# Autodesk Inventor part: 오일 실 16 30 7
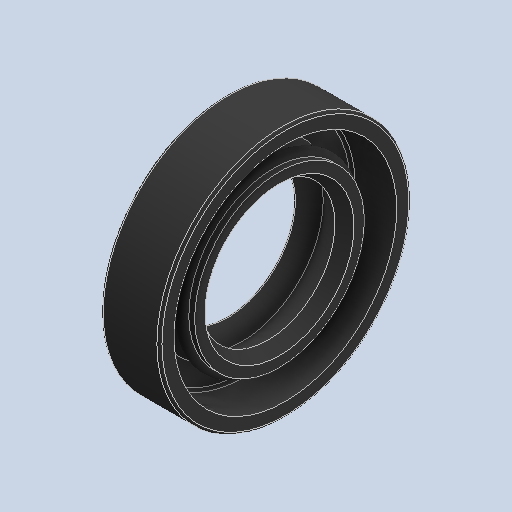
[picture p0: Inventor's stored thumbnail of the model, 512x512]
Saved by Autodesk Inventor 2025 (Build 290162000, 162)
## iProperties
Created: 2026-08
Part Number: 오일 실 16 30 7
Material: 고무
Description: 오일-실
Document SubType Name: Modeling
Designer: KDI
Density: 0.93 g/cm^3
Appearance: 기본값
Author: jhkim
Sending System: Autodesk Inventor 2027
Preprocessor: ST-DEVELOPER v20.1
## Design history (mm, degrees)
feature "Solid1"
node "솔리드1"
